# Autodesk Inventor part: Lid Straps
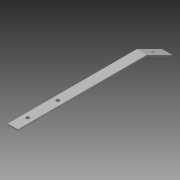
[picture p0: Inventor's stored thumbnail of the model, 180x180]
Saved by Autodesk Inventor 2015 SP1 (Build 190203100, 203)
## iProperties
Created: 2013-06
Part Number: Lid Straps
Material: Steel, Mild
Document SubType Name: Sheet Metal
Designer: 1103005
Density: 7.86 g/cm^3
Sheet Metal Rule: Default_mm
Appearance: Steel
Flat Pattern Width: 1 cm
Flat Pattern Length: 15.6939 cm
Flat Pattern Area: 15.6939 cm^2
Sheet Metal Width: 10.000 mm
Sheet Metal Length: 156.939 mm
Sheet Metal Area: 1569.392 mm^2
Author: 1103005
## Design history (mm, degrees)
node "Face1"
  sketch "Sketch1"
    geometry: L1 (5, -66)-(-5, -66); L2 (-5, -66)-(-5, 66); L3 (-5, 66)-(5, 66); L4 (5, 66)-(5, -66); L5 (5, -66)-(-5, 66); L6 (-5, -66)-(5, 66); 1 further point
    constraints: 12 end point, 2 midpoint, 2 parallel, 1 horizontal, 1 perpendicular
    dimensions: "d0" = 10 distance of L2.end L3.end; "d1" = 132 distance of L1.end L2.end
hole "Hole1" diameter "d5" = 3.5; stored, may be unused: countersink angle "d9" = 90 deg, drill point angle "d11" = 118 deg; dims "d3" = 15, "d6" = 6, "d7" = 4, "d8" = 2, "d10" = 1.5 (= Thickness), "d35" = 10
node "Contour Flange1"
  sketch "Sketch2"
    geometry: L1 (66, 0)-(88.361, -11.18); L2 (105.865, -4.3)-(38.786, 29.239) reference; L3 (66, 0)-(-66, 0) reference; L4 (66, 0)-(66, 1.5) reference; 2 further points
    constraints: 2 end point, 1 horizontal alignment, 1 midpoint, 1 parallel
    dimensions: "d12" = 25 distance of L1.start L1.end
sketch "Sketch3"
  geometry: L1 (10, 0)-(0, 0) reference; 3 further points
  constraints: 1 midpoint, 1 vertical alignment
  dimensions: "d22" = 15 distance from line of L1 point (5, -15)
hole "Hole2" sketch "Sketch3" at (5, -15) diameter "d23" = 3.5; stored, may be unused: countersink angle "d27" = 90 deg, drill point angle "d29" = 118 deg; dims "d24" = 6, "d25" = 4, "d26" = 2, "d28" = 1.5 (= Thickness)
pattern_linear "Rectangular Pattern1" dims "d32" = 30
body "Solid1"
face "Plate1" dims "Thickness" = 1.5
node "Reference1"
face "Plate2" dims "d13" = 1.5 (= BendReliefWidth), "d14" = 0.75 (= BendReliefDepth), "d15" = 3 (= MinimumRemnant), "d16" = 1.5 (= BendRadius), "d17" = 1.5 (= BendRadius), "d18" = 1.2, "d19" = 6 (= CornerReliefSize), "d20" = 1.5 (= GapSize), "d21" = 1.5 (= JacobiRadiusSize), "SeamGap" = 0.01, "Thickness" = 1.5
bend "Bend1" dims "d13" = 1.5 (= BendReliefWidth), "d14" = 0.75 (= BendReliefDepth), "d15" = 3 (= MinimumRemnant), "d16" = 1.5 (= BendRadius), "d17" = 1.5 (= BendRadius), "d18" = 1.2, "SeamGap" = 0.01, "Thickness" = 1.5
feature "Corner1" dims "d18" = 1.2, "d19" = 6 (= CornerReliefSize), "d20" = 1.5 (= GapSize), "d21" = 1.5 (= JacobiRadiusSize)
feature "Definition1"
other parameters: "BendRadius" = 1.5 (= Thickness), "BendReliefWidth" = 1.5 (= Thickness), "BendReliefDepth" = 0.75 (= 0.5 x Thickness), "CornerReliefSize" = 6 (= 4 x Thickness), "MinimumRemnant" = 3 (= 2 x Thickness), "TransitionRadius" = 1.5 (= BendRadius), "JacobiRadiusSize" = 1.5 (= BendRadius), "GapSize" = 1.5 (= Thickness), "d2" = 1.5 (= BendRadius), "BendRadius" = 1.5, "BendReliefDepth" = 0.75, "BendReliefWidth" = 1.5, "CornerReliefSize" = 6, "GapSize" = 1.5, "JacobiRadiusSize" = 1.5, "MinimumRemnant" = 3, "Thickness" = 1.5, "TransitionRadius" = 1.5
